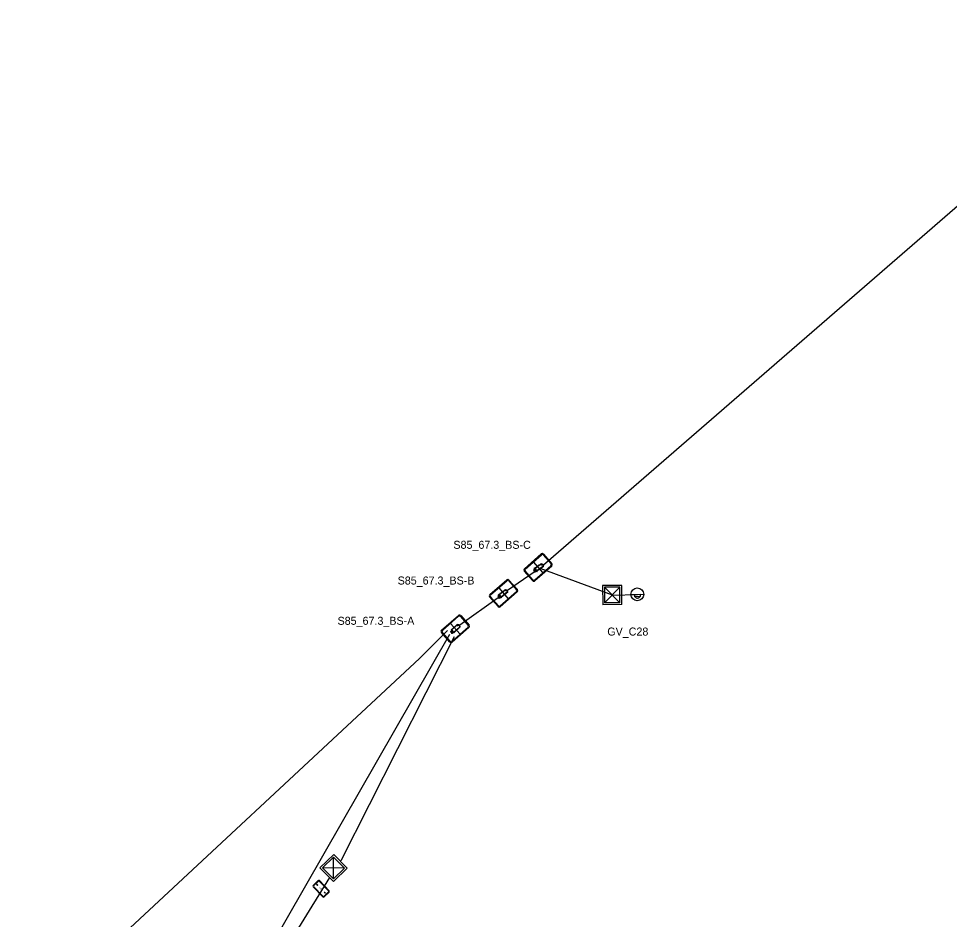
# Model space of a CAD drawing. Extents: x 1614474 to 1865144, y 1098877 to 1212550.
# Drawn here: x 1682075.1 to 1682365.6, y 1138327.9 to 1138609.1 of the extents above; entities that cross this region are included whole.
import ezdxf

# ---------------------------------------------------------------- set-up
doc = ezdxf.new("R2010")
doc.units = 0
for name, color, linetype in [('BFUSER_BUILDING', 7, 'Continuous'), ('BFUSER_DUCTENCLOSURE', 7, 'Continuous'), ('BFUSER_FIBERNODE', 7, 'Continuous'), ('BFUSER_FIBERNODENAME', 7, 'Continuous'), ('BFUSER_FIBERSPAN', 7, 'Continuous'), ('BFUSER_FIBERSPLICEENCLOSURE', 7, 'Continuous'), ('BFUSER_FIBERSPLICEENCLOSURENAME', 7, 'Continuous')]:
    doc.layers.add(name, color=color, linetype=linetype)

msp = doc.modelspace()

# ---------------------------------------------------------------- linework, layer by layer
at = {"layer": 'BFUSER_BUILDING'}
for p, q in [((1682263.35, 1138432.2), (1682257.35, 1138432.15)), ((1682257.35, 1138432.15), (1682257.4, 1138426.15)), ((1682262.75, 1138431.65), (1682257.96, 1138431.61)), ((1682257.96, 1138431.61), (1682262.79, 1138426.74)), ((1682257.96, 1138431.61), (1682258.01, 1138426.7)), ((1682262.75, 1138431.65), (1682258.01, 1138426.7)), ((1682262.79, 1138426.74), (1682262.75, 1138431.65)), ((1682263.4, 1138426.21), (1682263.35, 1138432.2)), ((1682263.4, 1138426.21), (1682257.4, 1138426.15)), ((1682262.79, 1138426.74), (1682258.01, 1138426.7)), ((1682169.14, 1138344.04), (1682173.44, 1138348.22)), ((1682169.96, 1138344.07), (1682173.38, 1138347.4)), ((1682173.38, 1138340.55), (1682173.38, 1138347.4)), ((1682176.81, 1138343.88), (1682173.38, 1138347.4)), ((1682177.62, 1138343.92), (1682173.44, 1138348.22)), ((1682169.14, 1138344.04), (1682173.32, 1138339.74)), ((1682176.81, 1138343.88), (1682169.96, 1138344.07)), ((1682169.96, 1138344.07), (1682173.38, 1138340.55)), ((1682173.32, 1138339.74), (1682177.62, 1138343.92)), ((1682173.38, 1138340.55), (1682176.81, 1138343.88))]:
    msp.add_line(p, q, dxfattribs=at)
at = {"layer": 'BFUSER_DUCTENCLOSURE'}
for p, q in [((1682235.74, 1138439.51), (1682238.71, 1138436.11)), ((1682224.96, 1138431.42), (1682227.93, 1138428.03)), ((1682209.89, 1138420.33), (1682212.86, 1138416.93)), ((1682169.51, 1138337.5), (1682169.51, 1138337.5))]:
    msp.add_line(p, q, dxfattribs=at)
for points in [[(1682232.95, 1138437.39), (1682238.22, 1138442)], [(1682233.21, 1138437.29), (1682238.28, 1138441.72)], [(1682238.84, 1138441.69), (1682241.28, 1138438.9)], [(1682238.92, 1138441.95), (1682241.56, 1138438.94)], [(1682235.54, 1138433.67), (1682232.9, 1138436.68)], [(1682235.61, 1138433.94), (1682233.17, 1138436.73)], [(1682236.18, 1138433.9), (1682241.25, 1138438.33)], [(1682241.51, 1138438.23), (1682236.24, 1138433.62)], [(1682222.16, 1138429.3), (1682227.43, 1138433.91)], [(1682222.42, 1138429.21), (1682227.49, 1138433.64)], [(1682228.06, 1138433.6), (1682230.5, 1138430.81)], [(1682228.14, 1138433.87), (1682230.77, 1138430.86)], [(1682224.75, 1138425.59), (1682222.11, 1138428.6)], [(1682224.83, 1138425.85), (1682222.39, 1138428.64)], [(1682225.39, 1138425.81), (1682230.46, 1138430.25)], [(1682230.72, 1138430.15), (1682225.45, 1138425.54)], [(1682207.09, 1138418.21), (1682212.36, 1138422.82)], [(1682207.36, 1138418.11), (1682212.42, 1138422.54)], [(1682212.99, 1138422.51), (1682215.43, 1138419.72)], [(1682213.07, 1138422.77), (1682215.7, 1138419.76)], [(1682210.32, 1138414.72), (1682215.39, 1138419.15)], [(1682215.65, 1138419.05), (1682210.39, 1138414.44)], [(1682209.68, 1138414.49), (1682207.05, 1138417.5)], [(1682209.76, 1138414.76), (1682207.32, 1138417.55)], [(1682168.56, 1138340.06), (1682166.98, 1138338.53)], [(1682166.98, 1138338.11), (1682170.04, 1138334.95)], [(1682168.59, 1138339.81), (1682167.23, 1138338.49)], [(1682167.23, 1138338.14), (1682170.08, 1138335.19)], [(1682171.8, 1138336.86), (1682168.95, 1138339.8)], [(1682172.05, 1138336.89), (1682168.99, 1138340.05)], [(1682170.43, 1138335.19), (1682171.79, 1138336.5)], [(1682170.46, 1138334.94), (1682172.04, 1138336.47)]]:
    msp.add_lwpolyline(points, dxfattribs=at)
for points in [[(1682168.19, 1138338.94), (1682168.5, 1138338.62), (1682168.42, 1138338.54), (1682168.11, 1138338.86)], [(1682170.57, 1138336.47), (1682170.88, 1138336.15), (1682170.81, 1138336.08), (1682170.5, 1138336.4)]]:
    msp.add_lwpolyline(points, close=True, dxfattribs=at)
for centre, radius, start, end in [((1682238.55, 1138441.62), 0.5, 41.184, 131.184), ((1682238.54, 1138441.42), 0.4, 41.184, 131.184), ((1682233.28, 1138437.01), 0.5, 131.184, 221.184), ((1682233.47, 1138436.99), 0.4, 131.184, 221.184), ((1682240.98, 1138438.63), 0.4, 311.184, 41.184), ((1682241.18, 1138438.61), 0.5, 311.184, 41.184), ((1682227.76, 1138433.54), 0.5, 41.1835, 131.1835), ((1682227.75, 1138433.34), 0.4, 41.1835, 131.1835), ((1682235.91, 1138434), 0.5, 221.184, 311.184), ((1682235.92, 1138434.2), 0.4, 221.184, 311.184), ((1682230.2, 1138430.55), 0.4, 311.1835, 41.1835), ((1682230.39, 1138430.53), 0.5, 311.1835, 41.1835), ((1682222.49, 1138428.93), 0.5, 131.1835, 221.1835), ((1682222.69, 1138428.91), 0.4, 131.1835, 221.1835), ((1682225.12, 1138425.92), 0.5, 221.1835, 311.1835), ((1682225.13, 1138426.12), 0.4, 221.1835, 311.1835), ((1682212.69, 1138422.44), 0.5, 41.1841, 131.1841), ((1682212.69, 1138422.24), 0.4, 41.1841, 131.1841), ((1682215.13, 1138419.45), 0.4, 311.1841, 41.1841), ((1682215.32, 1138419.43), 0.5, 311.1841, 41.1841), ((1682207.42, 1138417.83), 0.5, 131.1841, 221.1841), ((1682207.62, 1138417.81), 0.4, 131.1841, 221.1841), ((1682210.06, 1138414.82), 0.5, 221.1841, 311.1841), ((1682210.06, 1138415.02), 0.4, 221.1841, 311.1841), ((1682167.19, 1138338.32), 0.3, 134.0595, 224.0595), ((1682167.41, 1138338.32), 0.25, 134.0595, 224.0595), ((1682168.77, 1138339.85), 0.3, 44.0595, 134.0595), ((1682168.77, 1138339.63), 0.25, 44.0595, 134.0595), ((1682170.25, 1138335.15), 0.3, 224.0595, 314.0595), ((1682170.26, 1138335.37), 0.25, 224.0595, 314.0595), ((1682171.62, 1138336.68), 0.25, 314.0595, 44.0595), ((1682171.83, 1138336.68), 0.3, 314.0595, 44.0595)]:
    msp.add_arc(centre, radius, start, end, dxfattribs=at)
at = {"layer": 'BFUSER_FIBERNODE'}
msp.add_line((1682266.22, 1138429.32), (1682270.21, 1138429.44), dxfattribs=at)
msp.add_lwpolyline([(1682267.42, 1138429.36), (1682269.06, 1138429.41), (1682269.09, 1138428.69), (1682267.44, 1138428.64)], close=True, dxfattribs=at)
msp.add_circle((1682268.21, 1138429.38), 2, dxfattribs=at)
msp.add_arc((1682268.25, 1138429.22), 0.992, 215.5182, 327.8082, dxfattribs=at)
at = {"layer": 'BFUSER_FIBERSPAN'}
for p, q in [((1682227.65, 1138430.65), (1682236.04, 1138436.47)), ((1682260.43, 1138429.16), (1682238.18, 1138437.35)), ((1682212.76, 1138419.83), (1682224.75, 1138428.38)), ((1682260.43, 1138429.16), (1682268.24, 1138429.38)), ((1682211.08, 1138416.15), (1682175.61, 1138346.19))]:
    msp.add_line(p, q, dxfattribs=at)
for points in [[(1682238.94, 1138438.63), (1682238.94, 1138438.63), (1682497.36, 1138662.71), (1682700.63, 1138841.25), (1682834.77, 1138947.63), (1683367.31, 1139363.06), (1683511.85, 1139349.5), (1684213.91, 1139723.51), (1684216.77, 1139718.67)], [(1681025.2, 1137313.49), (1681561.79, 1137793.28), (1681610.98, 1137861.1), (1682200.25, 1138409.32), (1682208.93, 1138418.16)], [(1682209.63, 1138416.91), (1682119.3, 1138259.24), (1682213.25, 1138138.66), (1682153.28, 1138060.58), (1682150.86, 1138062.82)], [(1682172.11, 1138341.04), (1682121.21, 1138258.45), (1682105.38, 1138235.22)]]:
    msp.add_lwpolyline(points, dxfattribs=at)
at = {"layer": 'BFUSER_FIBERSPLICEENCLOSURE'}
for p, q in [((1682235.82, 1138436.98), (1682236.11, 1138437.2)), ((1682235.92, 1138436.85), (1682235.82, 1138436.98)), ((1682235.82, 1138436.96), (1682235.83, 1138436.97)), ((1682235.89, 1138436.86), (1682235.82, 1138436.96)), ((1682235.83, 1138436.97), (1682235.9, 1138436.87)), ((1682235.9, 1138436.87), (1682235.89, 1138436.86)), ((1682236.21, 1138437.07), (1682235.92, 1138436.85)), ((1682235.95, 1138436.81), (1682236.24, 1138437.02)), ((1682236.04, 1138436.68), (1682235.95, 1138436.81)), ((1682235.95, 1138436.79), (1682235.96, 1138436.8)), ((1682236.02, 1138436.69), (1682235.95, 1138436.79)), ((1682235.96, 1138436.8), (1682236.03, 1138436.69)), ((1682236.03, 1138436.69), (1682236.02, 1138436.69)), ((1682236.68, 1138436.47), (1682236.03, 1138437.35)), ((1682236.04, 1138437.53), (1682236.17, 1138437.62)), ((1682236.83, 1138436.45), (1682236.04, 1138437.53)), ((1682236.33, 1138436.89), (1682236.04, 1138436.68)), ((1682236.05, 1138437.33), (1682236.13, 1138437.4)), ((1682236.67, 1138436.48), (1682236.05, 1138437.33)), ((1682236.06, 1138436.65), (1682236.35, 1138436.86)), ((1682236.32, 1138436.3), (1682236.06, 1138436.65)), ((1682236.06, 1138436.63), (1682236.07, 1138436.64)), ((1682236.3, 1138436.31), (1682236.06, 1138436.63)), ((1682236.07, 1138436.64), (1682236.31, 1138436.32)), ((1682236.13, 1138437.4), (1682236.76, 1138436.55)), ((1682236.17, 1138437.62), (1682236.96, 1138436.54)), ((1682236.2, 1138437.06), (1682236.23, 1138437.02)), ((1682236.23, 1138437.53), (1682237.99, 1138438.82)), ((1682236.27, 1138437.48), (1682238.03, 1138438.77)), ((1682236.31, 1138436.32), (1682236.3, 1138436.31)), ((1682236.61, 1138436.52), (1682236.32, 1138436.3)), ((1682236.33, 1138436.89), (1682236.64, 1138436.52)), ((1682236.52, 1138437.86), (1682236.5, 1138437.84)), ((1682236.5, 1138437.84), (1682236.55, 1138437.77)), ((1682236.57, 1138437.78), (1682236.52, 1138437.86)), ((1682236.55, 1138437.77), (1682236.57, 1138437.78)), ((1682236.76, 1138436.55), (1682236.67, 1138436.48)), ((1682236.77, 1138438.05), (1682236.75, 1138438.03)), ((1682236.75, 1138438.03), (1682236.81, 1138437.96)), ((1682236.83, 1138437.97), (1682236.77, 1138438.05)), ((1682236.81, 1138437.96), (1682236.83, 1138437.97)), ((1682236.96, 1138436.54), (1682236.83, 1138436.45)), ((1682238.9, 1138438.19), (1682236.85, 1138436.69)), ((1682238.94, 1138438.13), (1682236.89, 1138436.63)), ((1682237.43, 1138438.52), (1682237.41, 1138438.51)), ((1682237.41, 1138438.51), (1682237.46, 1138438.44)), ((1682237.48, 1138438.45), (1682237.43, 1138438.52)), ((1682237.46, 1138438.44), (1682237.48, 1138438.45)), ((1682237.68, 1138438.71), (1682237.66, 1138438.7)), ((1682237.66, 1138438.7), (1682237.72, 1138438.62)), ((1682237.74, 1138438.64), (1682237.68, 1138438.71)), ((1682237.72, 1138438.62), (1682237.74, 1138438.64)), ((1682238.03, 1138438.77), (1682238.11, 1138438.66)), ((1682238.09, 1138438.81), (1682238.16, 1138438.7)), ((1682238.26, 1138438.69), (1682238.44, 1138438.82)), ((1682238.3, 1138438.63), (1682238.48, 1138438.76)), ((1682238.48, 1138438.76), (1682238.9, 1138438.19)), ((1682238.54, 1138438.8), (1682238.96, 1138438.23)), ((1682225.07, 1138429.38), (1682226.77, 1138430.74)), ((1682225.11, 1138429.32), (1682226.82, 1138430.68)), ((1682226.47, 1138430.61), (1682226.45, 1138430.6)), ((1682226.45, 1138430.6), (1682226.51, 1138430.53)), ((1682226.53, 1138430.54), (1682226.47, 1138430.61)), ((1682226.51, 1138430.53), (1682226.53, 1138430.54)), ((1682226.82, 1138430.68), (1682226.9, 1138430.58)), ((1682226.87, 1138430.73), (1682226.95, 1138430.62)), ((1682227.05, 1138430.61), (1682227.22, 1138430.75)), ((1682227.09, 1138430.56), (1682227.27, 1138430.7)), ((1682227.27, 1138430.7), (1682227.71, 1138430.14)), ((1682227.32, 1138430.74), (1682227.77, 1138430.18)), ((1682224.68, 1138428.81), (1682224.97, 1138429.04)), ((1682224.78, 1138428.68), (1682224.68, 1138428.81)), ((1682224.68, 1138428.79), (1682224.69, 1138428.8)), ((1682224.76, 1138428.69), (1682224.68, 1138428.79)), ((1682224.69, 1138428.8), (1682224.77, 1138428.7)), ((1682224.77, 1138428.7), (1682224.76, 1138428.69)), ((1682225.07, 1138428.91), (1682224.78, 1138428.68)), ((1682224.82, 1138428.64), (1682225.1, 1138428.87)), ((1682224.92, 1138428.51), (1682224.82, 1138428.64)), ((1682224.82, 1138428.62), (1682224.83, 1138428.63)), ((1682224.9, 1138428.52), (1682224.82, 1138428.62)), ((1682224.83, 1138428.63), (1682224.91, 1138428.53)), ((1682224.88, 1138429.36), (1682225, 1138429.46)), ((1682225.71, 1138428.32), (1682224.88, 1138429.36)), ((1682225.56, 1138428.33), (1682224.88, 1138429.19)), ((1682224.89, 1138429.17), (1682224.98, 1138429.23)), ((1682225.55, 1138428.34), (1682224.89, 1138429.17)), ((1682224.91, 1138428.53), (1682224.9, 1138428.52)), ((1682225.2, 1138428.74), (1682224.92, 1138428.51)), ((1682224.94, 1138428.49), (1682225.22, 1138428.71)), ((1682225.21, 1138428.15), (1682224.94, 1138428.49)), ((1682224.94, 1138428.46), (1682224.95, 1138428.47)), ((1682225.19, 1138428.15), (1682224.94, 1138428.46)), ((1682224.95, 1138428.47), (1682225.2, 1138428.16)), ((1682224.98, 1138429.23), (1682225.64, 1138428.41)), ((1682225, 1138429.46), (1682225.84, 1138428.42)), ((1682225.06, 1138428.9), (1682225.09, 1138428.86)), ((1682225.19, 1138428.73), (1682225.52, 1138428.38)), ((1682225.2, 1138428.16), (1682225.19, 1138428.15)), ((1682225.49, 1138428.37), (1682225.21, 1138428.15)), ((1682225.34, 1138429.71), (1682225.32, 1138429.7)), ((1682225.32, 1138429.7), (1682225.38, 1138429.62)), ((1682225.4, 1138429.64), (1682225.34, 1138429.71)), ((1682225.38, 1138429.62), (1682225.4, 1138429.64)), ((1682225.64, 1138428.41), (1682225.55, 1138428.34)), ((1682225.59, 1138429.91), (1682225.57, 1138429.89)), ((1682225.57, 1138429.89), (1682225.63, 1138429.82)), ((1682225.65, 1138429.84), (1682225.59, 1138429.91)), ((1682225.63, 1138429.82), (1682225.65, 1138429.84)), ((1682225.84, 1138428.42), (1682225.71, 1138428.32)), ((1682227.71, 1138430.14), (1682225.73, 1138428.55)), ((1682227.76, 1138430.09), (1682225.77, 1138428.5)), ((1682226.22, 1138430.42), (1682226.21, 1138430.4)), ((1682226.21, 1138430.4), (1682226.26, 1138430.33)), ((1682226.28, 1138430.34), (1682226.22, 1138430.42)), ((1682226.26, 1138430.33), (1682226.28, 1138430.34)), ((1682210.25, 1138418.36), (1682211.86, 1138419.83)), ((1682210.3, 1138418.31), (1682211.9, 1138419.78)), ((1682210.73, 1138418.93), (1682210.72, 1138418.91)), ((1682210.72, 1138418.91), (1682210.78, 1138418.84)), ((1682210.8, 1138418.86), (1682210.73, 1138418.93)), ((1682210.78, 1138418.84), (1682210.8, 1138418.86)), ((1682212.83, 1138419.3), (1682210.96, 1138417.59)), ((1682212.88, 1138419.25), (1682211.01, 1138417.53)), ((1682211.33, 1138419.48), (1682211.31, 1138419.46)), ((1682211.31, 1138419.46), (1682211.37, 1138419.39)), ((1682211.39, 1138419.41), (1682211.33, 1138419.48)), ((1682211.37, 1138419.39), (1682211.39, 1138419.41)), ((1682211.57, 1138419.69), (1682211.55, 1138419.67)), ((1682211.55, 1138419.67), (1682211.61, 1138419.61)), ((1682211.63, 1138419.62), (1682211.57, 1138419.69)), ((1682211.61, 1138419.61), (1682211.63, 1138419.62)), ((1682211.9, 1138419.78), (1682211.99, 1138419.69)), ((1682211.96, 1138419.83), (1682212.04, 1138419.73)), ((1682212.14, 1138419.73), (1682212.31, 1138419.88)), ((1682212.19, 1138419.68), (1682212.35, 1138419.83)), ((1682212.35, 1138419.83), (1682212.83, 1138419.3)), ((1682212.4, 1138419.88), (1682212.89, 1138419.35)), ((1682209.9, 1138417.77), (1682210.17, 1138418.02)), ((1682210.01, 1138417.65), (1682209.9, 1138417.77)), ((1682209.9, 1138417.75), (1682209.91, 1138417.76)), ((1682209.99, 1138417.66), (1682209.9, 1138417.75)), ((1682209.91, 1138417.76), (1682210, 1138417.66)), ((1682210, 1138417.66), (1682209.99, 1138417.66)), ((1682210.28, 1138417.9), (1682210.01, 1138417.65)), ((1682210.05, 1138417.61), (1682210.31, 1138417.86)), ((1682210.16, 1138417.49), (1682210.05, 1138417.61)), ((1682210.05, 1138417.59), (1682210.06, 1138417.6)), ((1682210.13, 1138417.5), (1682210.05, 1138417.59)), ((1682210.06, 1138418.33), (1682210.18, 1138418.44)), ((1682210.96, 1138417.35), (1682210.06, 1138418.33)), ((1682210.06, 1138417.6), (1682210.14, 1138417.51)), ((1682210.81, 1138417.35), (1682210.07, 1138418.16)), ((1682210.09, 1138418.14), (1682210.17, 1138418.21)), ((1682210.8, 1138417.36), (1682210.09, 1138418.14)), ((1682210.14, 1138417.51), (1682210.13, 1138417.5)), ((1682210.42, 1138417.74), (1682210.16, 1138417.49)), ((1682210.17, 1138418.21), (1682210.88, 1138417.44)), ((1682210.18, 1138418.44), (1682211.08, 1138417.46)), ((1682210.18, 1138417.47), (1682210.44, 1138417.7)), ((1682210.47, 1138417.15), (1682210.18, 1138417.47)), ((1682210.18, 1138417.44), (1682210.19, 1138417.45)), ((1682210.45, 1138417.15), (1682210.18, 1138417.44)), ((1682210.19, 1138417.45), (1682210.46, 1138417.16)), ((1682210.27, 1138417.89), (1682210.31, 1138417.85)), ((1682210.41, 1138417.73), (1682210.77, 1138417.4)), ((1682210.46, 1138417.16), (1682210.45, 1138417.15)), ((1682210.74, 1138417.39), (1682210.47, 1138417.15)), ((1682210.5, 1138418.71), (1682210.48, 1138418.7)), ((1682210.48, 1138418.7), (1682210.54, 1138418.63)), ((1682210.56, 1138418.65), (1682210.5, 1138418.71)), ((1682210.54, 1138418.63), (1682210.56, 1138418.65)), ((1682210.88, 1138417.44), (1682210.8, 1138417.36)), ((1682211.08, 1138417.46), (1682210.96, 1138417.35))]:
    msp.add_line(p, q, dxfattribs=at)
for centre, radius, start, end in [((1682236.1, 1138437.22), 0.0265, 306.223, 36.9132), ((1682236.22, 1138437.05), 0.0265, 35.5327, 126.223), ((1682236.22, 1138437.05), 0.0265, 306.223, 36.9132), ((1682236.35, 1138436.87), 0.0265, 35.5327, 126.223), ((1682236.63, 1138436.49), 0.0265, 35.5327, 126.223), ((1682238.03, 1138438.77), 0.0694, 36.223, 126.223), ((1682238.27, 1138438.48), 0.42, 55.1051, 123.2299), ((1682238.27, 1138438.48), 0.392, 61.2689, 120.1807), ((1682238.22, 1138438.74), 0.139, 216.223, 306.223), ((1682238.22, 1138438.74), 0.0694, 216.223, 306.223), ((1682238.48, 1138438.76), 0.0694, 36.1746, 126.223), ((1682238.12, 1138438.05), 0.857, 8.2335, 61.0662), ((1682238.9, 1138438.19), 0.0694, 306.223, 36.1746), ((1682226.82, 1138430.68), 0.0694, 38.6025, 128.6025), ((1682227.06, 1138430.41), 0.42, 57.4846, 125.6094), ((1682227.06, 1138430.41), 0.392, 63.6484, 122.5602), ((1682227.01, 1138430.67), 0.139, 218.6025, 308.6025), ((1682227.01, 1138430.67), 0.0694, 218.6025, 308.6025), ((1682227.27, 1138430.7), 0.0694, 38.5541, 128.6025), ((1682226.94, 1138429.97), 0.857, 10.613, 63.4457), ((1682224.95, 1138429.06), 0.0265, 308.6025, 39.2927), ((1682225.08, 1138428.89), 0.0265, 37.9122, 128.6025), ((1682225.08, 1138428.89), 0.0265, 308.6025, 39.2927), ((1682225.22, 1138428.72), 0.0265, 37.9122, 128.6025), ((1682225.51, 1138428.35), 0.0265, 37.9122, 128.6025), ((1682227.71, 1138430.14), 0.0694, 308.6025, 38.5541), ((1682211.9, 1138419.78), 0.0694, 42.4553, 132.4553), ((1682212.17, 1138419.53), 0.42, 61.3375, 129.4622), ((1682212.17, 1138419.53), 0.392, 67.5012, 126.413), ((1682212.09, 1138419.78), 0.139, 222.4553, 312.4553), ((1682212.09, 1138419.78), 0.0694, 222.4553, 312.4553), ((1682212.35, 1138419.83), 0.0694, 42.407, 132.4553), ((1682212.07, 1138419.08), 0.857, 14.4659, 67.2986), ((1682212.83, 1138419.3), 0.0694, 312.4553, 42.407), ((1682210.15, 1138418.03), 0.0265, 312.4553, 43.1456), ((1682210.29, 1138417.88), 0.0265, 41.765, 132.4553), ((1682210.3, 1138417.88), 0.0265, 312.4553, 43.1456), ((1682210.44, 1138417.72), 0.0265, 41.765, 132.4553), ((1682210.76, 1138417.37), 0.0265, 41.765, 132.4553)]:
    msp.add_arc(centre, radius, start, end, dxfattribs=at)

# ---------------------------------------------------------------- texts
at = {"layer": 'BFUSER_DUCTENCLOSURE'}
msp.add_text('ELEC.', height=0.417, rotation=314.0595, dxfattribs=at).set_placement((1682168.76, 1138337.93))
at = {"layer": 'BFUSER_FIBERNODENAME'}
msp.add_text('GV_C28', height=2.5, rotation=0.0002, dxfattribs=at).set_placement((1682258.84, 1138416.53))
at = {"layer": 'BFUSER_FIBERSPLICEENCLOSURENAME'}
for s, rotation, p in [('S85_67.3_BS-C', 0.0006, (1682210.8, 1138443.61)), ('S85_67.3_BS-B', 0.0011, (1682193.39, 1138432.46))]:
    msp.add_text(s, height=2.5, rotation=rotation, dxfattribs=at).set_placement(p)
msp.add_text('S85_67.3_BS-A', height=2.5, dxfattribs=at).set_placement((1682174.63, 1138419.89))

doc.saveas('drawing.dxf')
